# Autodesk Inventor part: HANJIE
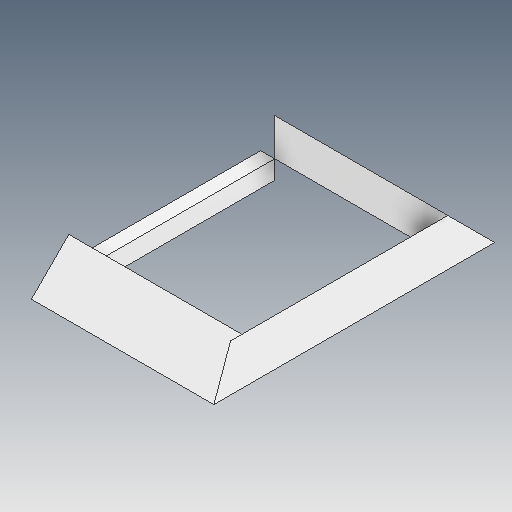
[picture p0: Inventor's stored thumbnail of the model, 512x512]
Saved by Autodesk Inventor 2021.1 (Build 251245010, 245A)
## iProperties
Created: 2021-05
Part Number: HANJIE
Material: Ogólny
Document SubType Name: Modeling
Designer: user
Density: 1 g/cm^3
Appearance: Domyślna
Author: user
Revision Number: ÈÎºÎ
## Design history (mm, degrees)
feature "ÊäÈë1"
feature "ÊäÈë2"
node "Bryła1"
node "Bryła2"
